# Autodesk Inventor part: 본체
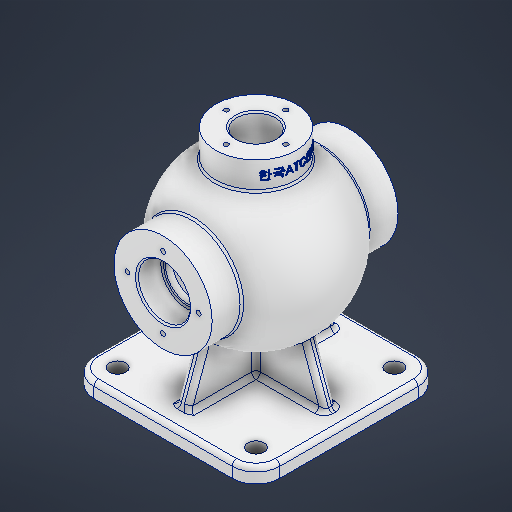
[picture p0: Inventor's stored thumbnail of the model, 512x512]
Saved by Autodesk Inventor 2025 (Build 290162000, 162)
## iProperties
Created: 2025-08
Part Number: 본체
Material: 알루미늄 6061
Document SubType Name: Modeling
Designer: infra023
Density: 2.7 g/cm^3
Appearance: 알루미늄 - 평지
Mass: 2028.23 g
Surface Area: 1139.74 cm^2
Volume: 751.195 cm^3
Author: infra023
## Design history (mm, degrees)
sketch "스케치1"
  geometry: L1 (-62.5, 62.5)-(62.5, 62.5); L2 (62.5, 62.5)-(62.5, -62.5); L3 (62.5, -62.5)-(-62.5, -62.5); L4 (-62.5, -62.5)-(-62.5, 62.5); L5 (-62.5, 62.5)-(62.5, -62.5); L6 (62.5, 62.5)-(-62.5, -62.5); 1 further point
  constraints: 12 end point, 2 midpoint, 2 parallel, 1 horizontal, 1 perpendicular
  dimensions: "d0" = 125 distance of L2.end L3.end; "d1" = 125 distance of L1.end L2.end
extrude "돌출1" new body sketch "스케치1" distance "d2" = 10; taper "d3" = 0 deg
sketch "스케치2"
  geometry: L1 (0, 62.5)-(0, -62.5) reference; L2 (10, 62.5)-(10, -62.5) reference; L3 (0, 62.5)-(0, -62.5) reference; L4 (0, -62.5)-(10, -62.5) reference; L5 (10, 62.5)-(10, -62.5) reference; L6 (0, 62.5)-(10, 62.5) reference; L7 (85, 54)-(85, -54); A1 r 54 centre (85, 0) between (85, 54) and (85, -54); 3 further points
  constraints: 2 end point, 2 midpoint, 2 point on circle, 1 centre point, 1 coincident, 1 horizontal alignment, 1 vertical
  dimensions: "d6" = 108 diameter of A1; "d7" = 85 distance from line of L1 A1.centre
revolve "회전1" sketch "스케치2" stored, may be unused: angle "d8" = 90 deg
node "작업 평면2"
sketch "스케치5"
  geometry: C1 r 33 at (0, 85); C2 r 54 at (0, 85) reference; 1 further point
  constraints: 1 centre point, 1 coincident
  dimensions: "d14" = 66 diameter of C1
extrude "돌출3" join sketch "스케치5" stored distance "d15" = 10; taper "d16" = 0 deg
sketch "스케치6"
  geometry: L1 (62.5, 10)-(-62.5, 10) reference; L2 (-50.5, 10)-(-37.385, 46.034); L3 (-62.5, 0)-(-62.5, 10) reference; L4 (-50.5, 10)-(0, 10); L5 (-37.385, 46.034)-(0, 46.034); L6 (0, 46.034)-(0, 10); 3 further points
  constraints: 8 end point, 1 horizontal, 1 midpoint, 1 perpendicular, 1 point on line, 2 other
  dimensions: "d17" = 12 distance of L1.end L2.start; "d18" = 20 deg angle of L3 L2
extrude "돌출4" join sketch "스케치6" stored distance "d19" = 8; taper "d20" = 0 deg
sketch "스케치8"
  geometry: L1 (-62.5, 10)-(62.5, 10) reference; L2 (50.5, 10)-(37.385, 46.034); L3 (62.5, 10)-(62.5, 30); L4 (37.385, 46.034)-(0, 46.034); L5 (0, 10)-(0, 31) reference; L6 (0, 46.034)-(0, 10); A1 r 54 centre (0, 85) between (37.385, 46.034) and (0, 31) reference; 1 further point
  constraints: 8 end point, 1 collinear, 1 horizontal, 1 point on circle, 1 point on line, 1 vertical
  dimensions: "d26" = 12 distance of L1.end L2.start; "d27" = 20 deg angle of L3 L2
extrude "돌출6" join sketch "스케치8" stored distance "d28" = 8; taper "d29" = 0 deg
sketch "스케치9"
  geometry: L1 (10, -62.5)-(10, 62.5) reference; L2 (10, -50.5)-(46.034, -37.385); L3 (0, -62.5)-(10, -62.5) reference; L4 (46.034, -4)-(46.034, 0) reference; L5 (46.034, -37.385)-(46.034, 0); L6 (46.034, 0)-(10, 0); A1 r 54 centre (85, 0) between (52, 42.743) and (118, 42.743) reference; 2 further points
  constraints: 6 end point, 1 midpoint, 1 point on circle, 1 point on line
  dimensions: "d30" = 12 distance of L1.start L2.start; "d31" = 20 deg angle of L3 L2
extrude "돌출7" join sketch "스케치9" stored distance "d32" = 8; taper "d33" = 0 deg
node "작업 평면3"
sketch "스케치10"
  geometry: C1 r 27 at (0, 0); 1 further point
  constraints: 1 centre point, 1 coincident
  dimensions: "d35" = 54 diameter of C1
extrude "돌출8" join sketch "스케치10" stored distance "d36" = 8; taper "d37" = 0 deg
sketch "스케치11"
  geometry: 1 further point
sketch "스케치12"
  geometry: L1 (-27, 131.765)-(27, 131.765) reference; L2 (0, 31)-(0, 46.034) reference; L3 (0, 31)-(0, 46.034) reference; L4 (-44, 85)-(44, 85); C1 r 44 at (0, 85); C2 r 44 at (0, 85); A1 r 54 centre (0, 85) between (-37.385, 46.034) and (0, 31) reference; A2 r 54 centre (0, 85) between (0, 31) and (37.385, 46.034) reference; A3 r 44 centre (0, 85) between (-44, 85) and (44, 85); 4 further points
  constraints: 3 centre point, 3 coincident, 3 concentric, 2 end point, 2 point on circle, 1 horizontal, 1 midpoint
  dimensions: "d98" = 88 diameter of C1; "d99" = 44 distance from line of point (44, 85) L2; "d100" = 46.76537 distance from line of point (44, 85) L1; "d101" = 44 distance from line of point (-44, 85) L2; "d102" = 46.76537 distance from line of point (-44, 85) L1
revolve "회전2" sketch "스케치12" stored, may be unused: angle "d38" = 90 deg
sketch "스케치13"
  geometry: 1 further point
hole "구멍1" sketch "스케치13" at (0, 0) diameter "d39" = 26; stored, may be unused: countersink angle "d43" = 90 deg, drill point angle "d45" = 118 deg; dims "d40" = 6, "d41" = 4, "d42" = 2, "d44" = 8
sketch "스케치14"
  geometry: C1 r 33 at (0, 0) reference; 1 further point
  node "투영된 루프3"
hole "구멍2" sketch "스케치14" diameter "d46" = 30; stored, may be unused: countersink angle "d50" = 90 deg, drill point angle "d52" = 118 deg; dims "d47" = 6, "d48" = 35, "d49" = 16, "d51" = 8
sketch "스케치15"
  geometry: L1 (0, 24)-(0, -24); L2 (-24, 0)-(24, 0); C1 r 17.5 at (0, 0) reference; C2 r 33 at (0, 0) reference; A1 r 24 centre (0, 0) between (0, 24) and (0, -24); 3 further points
  constraints: 4 end point, 4 point on circle, 3 coincident, 2 midpoint, 1 centre point, 1 horizontal, 1 vertical
  dimensions: "d53" = 48 diameter of A1
hole "구멍3" sketch "스케치15" at (0, 24), (-24, 0), (0, -24), (24, 0) diameter "d54" = 3.242; stored, may be unused: countersink angle "d58" = 90 deg, drill point angle "d60" = 118 deg; dims "d55" = 12, "d56" = 4, "d57" = 2, "d59" = 15
sketch "스케치16"
  geometry: L1 (-46.5, 46.5)-(46.5, 46.5); L2 (46.5, 46.5)-(46.5, -46.5); L3 (46.5, -46.5)-(-46.5, -46.5); L4 (-46.5, -46.5)-(-46.5, 46.5); L5 (-46.5, 46.5)-(46.5, -46.5); L6 (46.5, 46.5)-(-46.5, -46.5); 1 further point
  constraints: 12 end point, 2 midpoint, 2 parallel, 1 horizontal, 1 perpendicular
  dimensions: "d61" = 93 distance of L2.end L3.end; "d62" = 93 distance of L1.end L2.end
hole "구멍4" sketch "스케치16" at (-46.5, 46.5), (46.5, 46.5), (-46.5, -46.5), (46.5, -46.5) diameter "d63" = 11; stored, may be unused: countersink angle "d67" = 90 deg, drill point angle "d69" = 118 deg; dims "d64" = 12, "d65" = 4, "d66" = 2, "d68" = 8
sketch "스케치17"
  geometry: L1 (-37.385, 0)-(0, 0) reference; L2 (0, 20)-(0, -20); L3 (-20, 0)-(20, 0); A1 r 20 centre (0, 0) between (0, 20) and (0, -20); 2 further points
  constraints: 4 end point, 4 point on circle, 2 coincident, 2 midpoint, 2 point on line, 1 centre point, 1 vertical
  dimensions: "d70" = 40 diameter of A1
hole "구멍5" sketch "스케치17" at (0, 20), (-20, 0), (0, -20), (20, 0) diameter "d71" = 3.242; stored, may be unused: countersink angle "d75" = 90 deg, drill point angle "d77" = 118 deg; dims "d72" = 9, "d73" = 4, "d74" = 2, "d76" = 11
fillet "모깎기1" dims "d78" = 16
fillet "모깎기2" dims "d79" = 3
fillet "모깎기3" dims "d80" = 3
chamfer "모따기1" distance "d81" = 1; stored, may be unused: second distance "d82" = 2, angle "d83" = 45 deg
chamfer "모따기2" distance "d84" = 1; stored, may be unused: second distance "d85" = 2, angle "d86" = 45 deg
chamfer "모따기3" distance "d87" = 0.6; stored, may be unused: second distance "d88" = 2, angle "d89" = 45 deg
chamfer "모따기4" distance "d90" = 1; stored, may be unused: second distance "d91" = 2, angle "d92" = 45 deg
node "작업 평면4"
sketch "스케치18"
  geometry: L1 (150, 16.406)-(150, -17); L2 (150, -17)-(132, -17); L3 (132, -17)-(132, 16.406); L4 (132, 16.406)-(150, 16.406); L5 (150, -27)-(150, 27) reference; L6 (132.765, 27)-(132.765, -27) reference; 4 further points
  constraints: 3 midpoint, 1 vertical alignment, 2 other
  dimensions: "d94" = 9 horizontal distance of L5.end point (141, 16.406)
feature "엠보싱1" sketch "스케치18" dims "d8" = 90 deg, "d95" = 0.5, "d96" = 0
node "솔리드1"
mirror "미러2"
mirror "미러3"
mirror "미러4"
mirror "미러5"
node "투영된 루프1"
node "투영된 루프2"
node "투영된 루프4"
node "투영된 루프5"
feature "A9D066F2-1C7D-4E18-AEED-F7BC21143FA4" dims "d54" = 3.242, "d55" = 12, "d56" = 4, "d57" = 2, "d58" = 90 deg, "d59" = 15, "d60" = 118 deg
other parameters: "d13" = 62.5, "d93" = 27
